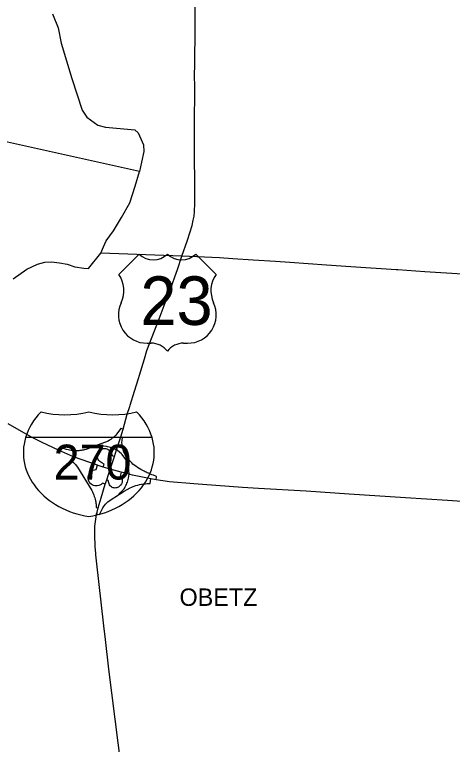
# Model space of a CAD drawing. Extents: x -1146 to -445, y -1283 to -822.
# Drawn here: x -894.1 to -862.8, y -1156.9 to -1104.6 of the extents above; entities that cross this region are included whole.
import ezdxf

# ---------------------------------------------------------------- set-up
doc = ezdxf.new("R2010")
doc.units = 0
for name, color, linetype in [('GM_X_Corporation_Text', 7, 'Continuous'), ('GM_X_Interchange_Ramps', 7, 'Continuous'), ('GM_X_Interstate_Route', 7, 'Continuous'), ('GM_X_Interstate_Shield', 7, 'Continuous'), ('GM_X_Township', 7, 'Continuous'), ('GM_X_US_Route', 7, 'Continuous'), ('GM_X_US_Shield', 7, 'Continuous')]:
    doc.layers.add(name, color=color, linetype=linetype)

msp = doc.modelspace()

# ---------------------------------------------------------------- linework, layer by layer
at = {"layer": 'GM_X_Interchange_Ramps'}
for points in [[(-886.357, -1134.273), (-886.529, -1134.227), (-886.758, -1134.547), (-886.818, -1134.621), (-886.881, -1134.694), (-886.949, -1134.765), (-887.027, -1134.839), (-887.097, -1134.898), (-887.168, -1134.954), (-887.244, -1135.008), (-887.327, -1135.061), (-887.438, -1135.123), (-888.404, -1135.504), (-889.006, -1135.728), (-889.12, -1135.757), (-889.205, -1135.776), (-889.292, -1135.791), (-889.371, -1135.803), (-889.447, -1135.812), (-889.535, -1135.82), (-889.644, -1135.825), (-889.757, -1135.826), (-889.849, -1135.823), (-889.959, -1135.815), (-890.073, -1135.802), (-890.19, -1135.783), (-890.292, -1135.763), (-890.399, -1135.736), (-890.883, -1135.569), (-890.993, -1135.789)], [(-883.999, -1137.894), (-883.96, -1137.658), (-884.193, -1137.577), (-884.295, -1137.539), (-884.407, -1137.495), (-884.491, -1137.459), (-884.55, -1137.434), (-884.633, -1137.396), (-884.697, -1137.366), (-884.769, -1137.33), (-884.843, -1137.293), (-885.078, -1137.172), (-885.327, -1137.011), (-885.441, -1136.937), (-885.562, -1136.848), (-885.656, -1136.771), (-885.742, -1136.693), (-885.835, -1136.601), (-885.926, -1136.501), (-885.974, -1136.444), (-886.042, -1136.358), (-886.091, -1136.289), (-886.125, -1136.24), (-886.208, -1136.109), (-886.294, -1135.916), (-886.328, -1135.833), (-886.355, -1135.757), (-886.387, -1135.644), (-886.409, -1135.545), (-886.422, -1135.466), (-886.434, -1135.357), (-886.439, -1135.244), (-886.41, -1134.869), (-886.521, -1134.835)], [(-886.605, -1138.942), (-886.634, -1138.895), (-886.487, -1138.768), (-886.415, -1138.69), (-886.334, -1138.595), (-886.287, -1138.55), (-886.243, -1138.481), (-886.2, -1138.407), (-886.155, -1138.32), (-886.117, -1138.238), (-886.082, -1138.153), (-886.053, -1138.068), (-885.961, -1137.781), (-885.926, -1137.507), (-885.924, -1137.489), (-885.939, -1137.219), (-885.961, -1136.965), (-886.058, -1136.718), (-886.126, -1136.53), (-886.216, -1136.381), (-886.298, -1136.261), (-886.433, -1136.096), (-886.508, -1136.014), (-886.59, -1135.954), (-886.785, -1135.789), (-886.838, -1135.767), (-886.964, -1135.714), (-887.105, -1135.66), (-887.175, -1135.63), (-887.265, -1135.595), (-887.352, -1135.566), (-887.463, -1135.536), (-887.556, -1135.516), (-887.734, -1135.49), (-887.841, -1135.494), (-887.969, -1135.503), (-888.092, -1135.515), (-888.203, -1135.526), (-888.381, -1135.566), (-888.404, -1135.504)], [(-887.792, -1136.986), (-887.724, -1136.773), (-887.875, -1136.694), (-888.013, -1136.595), (-888.088, -1136.508), (-888.141, -1136.437), (-888.175, -1136.36), (-888.2, -1136.267), (-888.206, -1136.189), (-888.202, -1136.112), (-888.185, -1136.036), (-888.159, -1135.967), (-888.128, -1135.909), (-888.085, -1135.85), (-888.037, -1135.8), (-887.979, -1135.754), (-887.911, -1135.715), (-887.838, -1135.687), (-887.756, -1135.669), (-887.667, -1135.665), (-887.602, -1135.671), (-887.532, -1135.688), (-887.47, -1135.712), (-887.418, -1135.74), (-887.365, -1135.776), (-887.314, -1135.823), (-887.277, -1135.866), (-887.242, -1135.917), (-887.195, -1136.009), (-887.149, -1136.172), (-886.977, -1136.231)], [(-889.908, -1136.261), (-890.023, -1136.568), (-889.911, -1136.663), (-889.858, -1136.712), (-889.811, -1136.759), (-889.763, -1136.81), (-889.71, -1136.873), (-889.624, -1136.986), (-888.606, -1138.674), (-888.559, -1138.76), (-888.522, -1138.837), (-888.48, -1138.931), (-888.449, -1139.008), (-888.419, -1139.093), (-888.389, -1139.184), (-888.358, -1139.298), (-888.335, -1139.401), (-888.318, -1139.491), (-888.306, -1139.57), (-888.297, -1139.653), (-888.297, -1139.891), (-888.15, -1139.921)], [(-887.631, -1138.217), (-887.834, -1138.151), (-887.935, -1138.238), (-888.024, -1138.289), (-888.104, -1138.32), (-888.205, -1138.342), (-888.282, -1138.346), (-888.385, -1138.335), (-888.479, -1138.309), (-888.569, -1138.267), (-888.643, -1138.217), (-888.729, -1138.132), (-888.786, -1138.049), (-888.84, -1137.921), (-888.861, -1137.809), (-888.861, -1137.703), (-888.842, -1137.599), (-888.792, -1137.476), (-888.713, -1137.365), (-888.606, -1137.271), (-888.5, -1137.214), (-888.411, -1137.185), (-888.293, -1137.168), (-888.195, -1136.862)], [(-886.502, -1137.348), (-886.568, -1137.639), (-886.48, -1137.722), (-886.424, -1137.856), (-886.419, -1137.97), (-886.434, -1138.099), (-886.475, -1138.203), (-886.545, -1138.29), (-886.584, -1138.339), (-886.631, -1138.384), (-886.687, -1138.425), (-886.75, -1138.456), (-886.808, -1138.476), (-886.873, -1138.489), (-886.936, -1138.493), (-886.995, -1138.488), (-887.074, -1138.47), (-887.138, -1138.444), (-887.196, -1138.41), (-887.252, -1138.364), (-887.288, -1138.327), (-887.331, -1138.266), (-887.364, -1138.199), (-887.386, -1138.131), (-887.416, -1137.942), (-887.53, -1137.908)], [(-888.257, -1140.344), (-888.046, -1140.386), (-887.914, -1140.1), (-887.867, -1140.011), (-887.808, -1139.912), (-887.757, -1139.836), (-887.69, -1139.746), (-887.613, -1139.654), (-887.521, -1139.556), (-887.443, -1139.482), (-887.344, -1139.398), (-886.605, -1138.942), (-886.289, -1138.706), (-885.843, -1138.47), (-885.727, -1138.42), (-885.635, -1138.384), (-885.529, -1138.345), (-885.436, -1138.315), (-885.309, -1138.279), (-885.187, -1138.249), (-885.036, -1138.218), (-884.892, -1138.196), (-884.759, -1138.18), (-884.644, -1138.172), (-884.425, -1138.164), (-884.369, -1137.831)]]:
    msp.add_lwpolyline(points, dxfattribs=at)
at = {"layer": 'GM_X_Interstate_Route'}
for points in [[(-889.908, -1136.261), (-890.993, -1135.789), (-892.156, -1135.231), (-892.864, -1134.871), (-893.811, -1134.345), (-894.588, -1133.882)], [(-888.061, -1136.904), (-888.195, -1136.862), (-889.908, -1136.261)], [(-887.277, -1137.135), (-887.792, -1136.986), (-888.061, -1136.904)], [(-885.679, -1137.562), (-885.861, -1137.525), (-885.926, -1137.507), (-886.502, -1137.348), (-887.277, -1137.135)], [(-850.255, -1140.217), (-850.957, -1140.159), (-856.794, -1139.812), (-863.126, -1139.382), (-866.131, -1139.196), (-870.172, -1138.941), (-873.251, -1138.719), (-876.652, -1138.518), (-877.807, -1138.452), (-880.683, -1138.232), (-881.301, -1138.185), (-883.025, -1138.058), (-883.999, -1137.894), (-884.369, -1137.831), (-885.679, -1137.562)]]:
    msp.add_lwpolyline(points, dxfattribs=at)
at = {"layer": 'GM_X_Interstate_Shield'}
msp.add_line((-884.28, -1134.876), (-893.345, -1134.876), dxfattribs=at)
msp.add_line((-884.28, -1134.876), (-893.345, -1134.876), dxfattribs=at)
for centre, start_param, end_param in [((-887.64, -1135.947), 2.47259, 2.911027), ((-890.524, -1128.557), 4.415841, 5.008937), ((-887.1, -1128.557), 4.415841, 5.008937), ((-889.984, -1135.947), 0.230566, 0.669003), ((-887.64, -1135.947), 2.911027, 4.511031), ((-889.984, -1135.947), 4.913747, 6.513751)]:
    msp.add_ellipse(centre, major_axis=(5.859, 0), ratio=0.8, start_param=start_param, end_param=end_param, dxfattribs=at)
at = {"layer": 'GM_X_Township'}
for points in [[(-891.411, -1104.525), (-891.013, -1105.536), (-890.797, -1106.62), (-890.038, -1109.149), (-889.279, -1111.425), (-888.954, -1111.93), (-888.159, -1112.508), (-887.617, -1112.653), (-885.522, -1112.833), (-885.269, -1113.05), (-884.908, -1113.917), (-884.872, -1114.387), (-885.052, -1115.145), (-885.182, -1115.826), (-902.183, -1112.045), (-904.358, -1111.689), (-910.289, -1110.249), (-915.786, -1108.893), (-917.339, -1108.257), (-921.29, -1107.327), (-927.148, -1105.948)], [(-894.228, -1123.509), (-893.253, -1122.822), (-892.494, -1122.461), (-891.952, -1122.316), (-891.483, -1122.28), (-890.905, -1122.353), (-890.363, -1122.461), (-889.821, -1122.642), (-889.171, -1122.75), (-888.845, -1122.768), (-887.957, -1121.659), (-887.769, -1121.22), (-887.581, -1120.781), (-887.039, -1120.058), (-886.461, -1119.119), (-885.883, -1118.071), (-885.486, -1116.879), (-885.182, -1115.826)], [(-835.589, -1125.008), (-835.585, -1124.955), (-835.644, -1124.951), (-838.263, -1124.769), (-839.555, -1124.672), (-842.354, -1124.475), (-843.569, -1124.413), (-848.745, -1124.067), (-855.341, -1123.619), (-862.055, -1123.177), (-864.742, -1123.001), (-866.693, -1122.873), (-866.806, -1122.867), (-870.047, -1122.655), (-871.799, -1122.523), (-874.423, -1122.339), (-875.436, -1122.275), (-877.054, -1122.178), (-878.503, -1122.082), (-879.46, -1122.01), (-882.142, -1121.871), (-887.957, -1121.659)]]:
    msp.add_lwpolyline(points, dxfattribs=at)
at = {"layer": 'GM_X_US_Route'}
for points in [[(-882.142, -1121.871), (-881.748, -1120.734), (-881.408, -1119.689), (-881.331, -1119.308), (-881.279, -1119.013), (-881.245, -1118.691), (-881.23, -1118.11), (-881.242, -1113.265), (-881.235, -1112.383), (-881.239, -1111.597), (-881.231, -1110.733), (-881.232, -1109.748), (-881.238, -1108.948), (-881.239, -1108.76), (-881.231, -1108.34), (-881.222, -1107.566), (-881.206, -1106.142), (-881.208, -1105.866), (-881.2, -1104.366), (-881.2, -1103.556), (-881.197, -1102.695), (-881.19, -1101.296), (-881.187, -1101.067)], [(-882.999, -1124.314), (-882.657, -1123.365), (-882.471, -1122.844), (-882.142, -1121.871)], [(-883.275, -1125.04), (-883.065, -1124.497), (-882.999, -1124.314)], [(-883.786, -1126.37), (-883.565, -1125.791), (-883.275, -1125.04)], [(-885.184, -1130.404), (-885.184, -1130.403), (-884.83, -1129.237), (-884.651, -1128.633), (-883.786, -1126.37)], [(-885.886, -1132.659), (-885.85, -1132.546), (-885.536, -1131.563), (-885.259, -1130.651), (-885.184, -1130.404)], [(-887.164, -1136.796), (-886.977, -1136.231), (-886.838, -1135.767), (-886.521, -1134.835), (-886.357, -1134.273), (-886.059, -1133.201), (-885.886, -1132.659)], [(-887.277, -1137.135), (-887.164, -1136.796)], [(-888.318, -1143.153), (-888.367, -1142.695), (-888.393, -1141.817), (-888.37, -1141.227), (-888.289, -1140.554), (-888.257, -1140.344), (-888.225, -1140.214), (-888.15, -1139.921), (-887.937, -1139.196), (-887.631, -1138.217), (-887.53, -1137.908), (-887.277, -1137.135)], [(-888.304, -1143.287), (-888.318, -1143.153)], [(-884.865, -1174.406), (-884.861, -1174.379), (-884.819, -1173.77), (-884.797, -1172.996), (-884.81, -1172.5), (-884.833, -1172.099), (-884.896, -1171.121), (-885.201, -1169.039), (-885.447, -1167.122), (-885.773, -1164.318), (-886.055, -1161.88), (-886.714, -1156.738), (-887.382, -1151.47), (-887.616, -1149.346), (-887.728, -1148.358), (-888.258, -1143.708), (-888.304, -1143.287)]]:
    msp.add_lwpolyline(points, dxfattribs=at)
at = {"layer": 'GM_X_US_Shield'}
for p, q in [((-885.216, -1121.735), (-886.666, -1123.185)), ((-879.705, -1123.185), (-881.155, -1121.735)), ((-884.636, -1128.115), (-884.346, -1128.115)), ((-882.026, -1128.115), (-881.736, -1128.115))]:
    msp.add_line(p, q, dxfattribs=at)
for centre, radius, start, end in [((-884.201, -1120.699), 1.45, 225.573, 314.427), ((-882.171, -1120.699), 1.45, 225.573, 314.427), ((-888.329, -1124.349), 2.03, 334.5471, 35.0009), ((-878.042, -1124.349), 2.03, 144.9991, 205.4529), ((-884.659, -1126.085), 2.03, 154.8319, 270.6383), ((-881.713, -1126.085), 2.03, 269.3617, 25.1681), ((-884.346, -1129.566), 1.45, 36.8699, 90), ((-882.026, -1129.566), 1.45, 90, 143.1301)]:
    msp.add_arc(centre, radius, start, end, dxfattribs=at)

# ---------------------------------------------------------------- texts
at = {"layer": 'GM_X_Corporation_Text'}
msp.add_text('OBETZ', height=1.25, rotation=0, dxfattribs=at).set_placement((-882.317, -1146.934))
at = {"layer": 'GM_X_Interstate_Shield'}
msp.add_text('270', height=2.5, dxfattribs=at).set_placement((-891.337, -1137.884))
at = {"layer": 'GM_X_US_Shield'}
msp.add_text('23', height=3.4805, dxfattribs=at).set_placement((-885.123, -1126.81))

doc.saveas('drawing.dxf')
